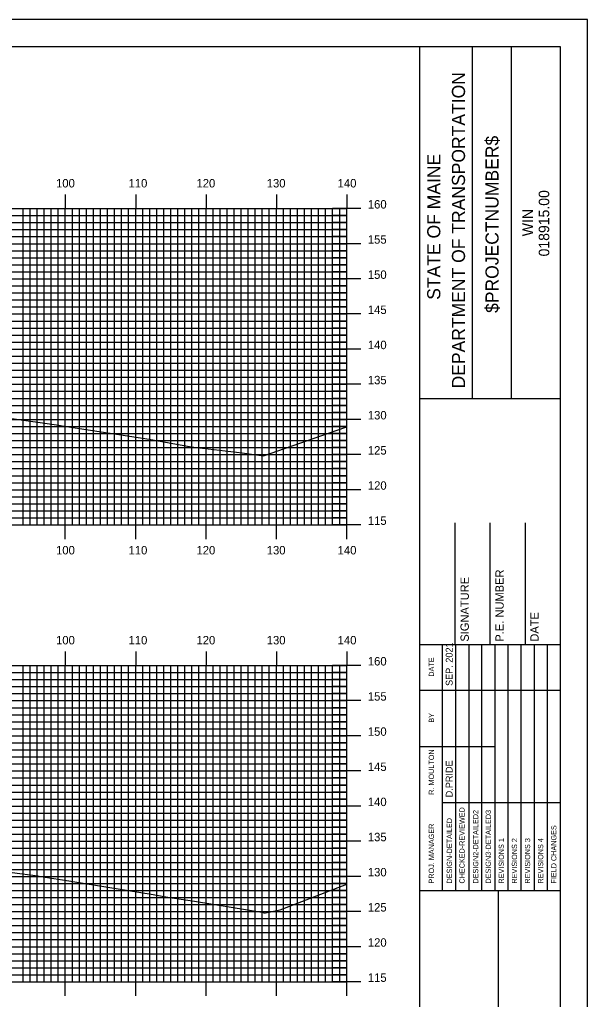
# Model space of a CAD drawing. Extents: x 851533 to 851876, y 366605 to 366825.
# Drawn here: x 851792 to 851872.7, y 366685.6 to 366824.9 of the extents above; entities that cross this region are included whole.
import ezdxf

# ---------------------------------------------------------------- set-up
doc = ezdxf.new("R2010")
doc.units = 0
for name, color, linetype in [('BORDER', 7, 'Continuous'), ('H_V ANNOTATION', 7, 'Continuous'), ('MAJOR', 7, 'Continuous'), ('MINOR', 7, 'Continuous'), ('PLOT BOUNDARY', 7, 'Continuous'), ('S_Roadway_Centerline', 7, 'Continuous')]:
    doc.layers.add(name, color=color, linetype=linetype)

msp = doc.modelspace()

# ---------------------------------------------------------------- linework, layer by layer
at = {"layer": 'BORDER'}
for p, q in [((851848.85, 366611.06), (851848.85, 366821.06)), ((851856.31, 366771.05), (851856.31, 366821.05)), ((851861.9, 366771.05), (851861.9, 366821.05)), ((851848.85, 366771.04), (851868.85, 366771.04)), ((851853.85, 366736.06), (851853.85, 366753.36)), ((851858.85, 366736.06), (851858.85, 366753.36)), ((851863.85, 366736.06), (851863.85, 366753.36)), ((851848.85, 366736.06), (851868.85, 366736.06)), ((851848.85, 366701.06), (851868.85, 366701.06)), ((851860.03, 366631.06), (851860.03, 366701.06))]:
    msp.add_line(p, q, dxfattribs=at)
msp.add_lwpolyline([(851548.85, 366611.06), (851868.85, 366611.06), (851868.85, 366821.06), (851548.85, 366821.06)], close=True, dxfattribs=at)
for points in [[(851852.08, 366729.56), (851852.08, 366736.06)], [(851853.95, 366701.07), (851853.95, 366736.06)], [(851855.81, 366736.06), (851855.81, 366701.07)], [(851857.67, 366701.07), (851857.67, 366736.06)], [(851859.54, 366701.07), (851859.54, 366736.06)], [(851861.4, 366701.07), (851861.4, 366736.06)], [(851863.26, 366701.07), (851863.26, 366736.06)], [(851865.13, 366701.07), (851865.13, 366736.06)], [(851866.99, 366701.07), (851866.99, 366736.06)], [(851852.08, 366701.07), (851852.08, 366734.65)], [(851848.85, 366729.56), (851868.85, 366729.56)], [(851848.85, 366721.56), (851852.08, 366721.56)], [(851852.08, 366721.56), (851859.53, 366721.56)], [(851852.08, 366713.56), (851868.85, 366713.56)]]:
    msp.add_lwpolyline(points, dxfattribs=at)
at = {"layer": 'MAJOR'}
for p, q in [((851798.45, 366800.06), (851798.45, 366798.06)), ((851808.45, 366800.06), (851808.45, 366798.06)), ((851818.45, 366800.06), (851818.45, 366798.06)), ((851828.45, 366800.06), (851828.45, 366798.06)), ((851838.45, 366800.06), (851838.45, 366798.06)), ((851558.45, 366798.06), (851838.45, 366798.06)), ((851558.45, 366798.06), (851838.45, 366798.06)), ((851798.45, 366753.06), (851798.45, 366798.06)), ((851808.45, 366753.06), (851808.45, 366798.06)), ((851818.45, 366753.06), (851818.45, 366798.06)), ((851828.45, 366753.06), (851828.45, 366798.06)), ((851840.46, 366798.06), (851836.45, 366798.06)), ((851838.45, 366753.06), (851838.45, 366798.06)), ((851838.45, 366753.06), (851838.45, 366798.06)), ((851558.45, 366793.06), (851838.45, 366793.06)), ((851840.46, 366793.06), (851836.45, 366793.06)), ((851558.45, 366788.06), (851838.45, 366788.06)), ((851840.46, 366788.06), (851836.45, 366788.06)), ((851558.45, 366783.06), (851838.45, 366783.06)), ((851840.46, 366783.06), (851836.45, 366783.06)), ((851558.45, 366778.06), (851838.45, 366778.06)), ((851840.46, 366778.06), (851836.45, 366778.06)), ((851558.45, 366773.06), (851838.45, 366773.06)), ((851840.46, 366773.06), (851836.45, 366773.06)), ((851558.45, 366768.06), (851838.45, 366768.06)), ((851840.46, 366768.06), (851836.45, 366768.06)), ((851558.45, 366763.06), (851838.45, 366763.06)), ((851840.46, 366763.06), (851836.45, 366763.06)), ((851558.45, 366758.06), (851838.45, 366758.06)), ((851840.46, 366758.06), (851836.45, 366758.06)), ((851558.45, 366753.06), (851838.45, 366753.06)), ((851558.45, 366753.06), (851838.45, 366753.06)), ((851798.45, 366751.05), (851798.45, 366753.06)), ((851808.45, 366751.05), (851808.45, 366753.06)), ((851818.45, 366751.05), (851818.45, 366753.06)), ((851828.45, 366751.05), (851828.45, 366753.06)), ((851840.46, 366753.06), (851836.45, 366753.06)), ((851838.45, 366751.05), (851838.45, 366753.06)), ((851798.45, 366735.06), (851798.45, 366733.06)), ((851808.45, 366735.06), (851808.45, 366733.06)), ((851818.45, 366735.06), (851818.45, 366733.06)), ((851828.45, 366735.06), (851828.45, 366733.06)), ((851838.45, 366735.06), (851838.45, 366733.06)), ((851558.45, 366733.06), (851838.45, 366733.06)), ((851558.45, 366733.06), (851838.45, 366733.06)), ((851798.45, 366688.06), (851798.45, 366733.06)), ((851808.45, 366688.06), (851808.45, 366733.06)), ((851818.45, 366688.06), (851818.45, 366733.06)), ((851828.45, 366688.06), (851828.45, 366733.06)), ((851840.46, 366733.06), (851836.45, 366733.06)), ((851838.45, 366688.06), (851838.45, 366733.06)), ((851838.45, 366688.06), (851838.45, 366733.06)), ((851558.45, 366728.06), (851838.45, 366728.06)), ((851840.46, 366728.06), (851836.45, 366728.06)), ((851558.45, 366723.06), (851838.45, 366723.06)), ((851840.46, 366723.06), (851836.45, 366723.06)), ((851558.45, 366718.06), (851838.45, 366718.06)), ((851840.46, 366718.06), (851836.45, 366718.06)), ((851558.45, 366713.06), (851838.45, 366713.06)), ((851840.46, 366713.06), (851836.45, 366713.06)), ((851558.45, 366708.06), (851838.45, 366708.06)), ((851840.46, 366708.06), (851836.45, 366708.06)), ((851558.45, 366703.06), (851838.45, 366703.06)), ((851840.46, 366703.06), (851836.45, 366703.06)), ((851558.45, 366698.06), (851838.45, 366698.06)), ((851840.46, 366698.06), (851836.45, 366698.06)), ((851558.45, 366693.06), (851838.45, 366693.06)), ((851840.46, 366693.06), (851836.45, 366693.06)), ((851558.45, 366688.06), (851838.45, 366688.06)), ((851558.45, 366688.06), (851838.45, 366688.06)), ((851798.45, 366686.05), (851798.45, 366688.06)), ((851808.45, 366686.05), (851808.45, 366688.06)), ((851818.45, 366686.05), (851818.45, 366688.06)), ((851828.45, 366686.05), (851828.45, 366688.06)), ((851840.46, 366688.06), (851836.45, 366688.06)), ((851838.45, 366686.05), (851838.45, 366688.06))]:
    msp.add_line(p, q, dxfattribs=at)
at = {"layer": 'MINOR'}
for p, q in [((851558.45, 366797.06), (851838.45, 366797.06)), ((851792.45, 366753.06), (851792.45, 366798.06)), ((851793.45, 366753.06), (851793.45, 366798.06)), ((851794.45, 366753.06), (851794.45, 366798.06)), ((851795.45, 366753.06), (851795.45, 366798.06)), ((851796.45, 366753.06), (851796.45, 366798.06)), ((851797.45, 366753.06), (851797.45, 366798.06)), ((851799.45, 366753.06), (851799.45, 366798.06)), ((851800.45, 366753.06), (851800.45, 366798.06)), ((851801.45, 366753.06), (851801.45, 366798.06)), ((851802.45, 366753.06), (851802.45, 366798.06)), ((851803.45, 366753.06), (851803.45, 366798.06)), ((851804.45, 366753.06), (851804.45, 366798.06)), ((851805.45, 366753.06), (851805.45, 366798.06)), ((851806.45, 366753.06), (851806.45, 366798.06)), ((851807.45, 366753.06), (851807.45, 366798.06)), ((851809.45, 366753.06), (851809.45, 366798.06)), ((851810.45, 366753.06), (851810.45, 366798.06)), ((851811.45, 366753.06), (851811.45, 366798.06)), ((851812.45, 366753.06), (851812.45, 366798.06)), ((851813.45, 366753.06), (851813.45, 366798.06)), ((851814.45, 366753.06), (851814.45, 366798.06)), ((851815.45, 366753.06), (851815.45, 366798.06)), ((851816.45, 366753.06), (851816.45, 366798.06)), ((851817.45, 366753.06), (851817.45, 366798.06)), ((851819.45, 366753.06), (851819.45, 366798.06)), ((851820.45, 366753.06), (851820.45, 366798.06)), ((851821.45, 366753.06), (851821.45, 366798.06)), ((851822.45, 366753.06), (851822.45, 366798.06)), ((851823.45, 366753.06), (851823.45, 366798.06)), ((851824.45, 366753.06), (851824.45, 366798.06)), ((851825.45, 366753.06), (851825.45, 366798.06)), ((851826.45, 366753.06), (851826.45, 366798.06)), ((851827.45, 366753.06), (851827.45, 366798.06)), ((851829.45, 366753.06), (851829.45, 366798.06)), ((851830.45, 366753.06), (851830.45, 366798.06)), ((851831.45, 366753.06), (851831.45, 366798.06)), ((851832.45, 366753.06), (851832.45, 366798.06)), ((851833.45, 366753.06), (851833.45, 366798.06)), ((851834.45, 366753.06), (851834.45, 366798.06)), ((851835.45, 366753.06), (851835.45, 366798.06)), ((851836.45, 366753.06), (851836.45, 366798.06)), ((851838.45, 366797.06), (851836.45, 366797.06)), ((851837.45, 366753.06), (851837.45, 366798.06)), ((851558.45, 366796.06), (851838.45, 366796.06)), ((851838.45, 366796.06), (851836.45, 366796.06)), ((851558.45, 366795.06), (851838.45, 366795.06)), ((851558.45, 366794.06), (851838.45, 366794.06)), ((851838.45, 366795.06), (851836.45, 366795.06)), ((851838.45, 366794.06), (851836.45, 366794.06)), ((851558.45, 366792.06), (851838.45, 366792.06)), ((851838.45, 366792.06), (851836.45, 366792.06)), ((851558.45, 366791.06), (851838.45, 366791.06)), ((851558.45, 366790.06), (851838.45, 366790.06)), ((851838.45, 366791.06), (851836.45, 366791.06)), ((851838.45, 366790.06), (851836.45, 366790.06)), ((851558.45, 366789.06), (851838.45, 366789.06)), ((851838.45, 366789.06), (851836.45, 366789.06)), ((851558.45, 366787.06), (851838.45, 366787.06)), ((851838.45, 366787.06), (851836.45, 366787.06)), ((851558.45, 366786.06), (851838.45, 366786.06)), ((851838.45, 366786.06), (851836.45, 366786.06)), ((851558.45, 366785.06), (851838.45, 366785.06)), ((851838.45, 366785.06), (851836.45, 366785.06)), ((851558.45, 366784.06), (851838.45, 366784.06)), ((851838.45, 366784.06), (851836.45, 366784.06)), ((851558.45, 366782.06), (851838.45, 366782.06)), ((851838.45, 366782.06), (851836.45, 366782.06)), ((851558.45, 366781.06), (851838.45, 366781.06)), ((851558.45, 366780.06), (851838.45, 366780.06)), ((851838.45, 366781.06), (851836.45, 366781.06)), ((851838.45, 366780.06), (851836.45, 366780.06)), ((851558.45, 366779.06), (851838.45, 366779.06)), ((851838.45, 366779.06), (851836.45, 366779.06)), ((851558.45, 366777.06), (851838.45, 366777.06)), ((851558.45, 366776.06), (851838.45, 366776.06)), ((851838.45, 366777.06), (851836.45, 366777.06)), ((851838.45, 366776.06), (851836.45, 366776.06)), ((851558.45, 366775.06), (851838.45, 366775.06)), ((851838.45, 366775.06), (851836.45, 366775.06)), ((851558.45, 366774.06), (851838.45, 366774.06)), ((851838.45, 366774.06), (851836.45, 366774.06)), ((851558.45, 366772.06), (851838.45, 366772.06)), ((851838.45, 366772.06), (851836.45, 366772.06)), ((851558.45, 366771.06), (851838.45, 366771.06)), ((851838.45, 366771.06), (851836.45, 366771.06)), ((851558.45, 366770.06), (851838.45, 366770.06)), ((851558.45, 366769.06), (851838.45, 366769.06)), ((851838.45, 366770.06), (851836.45, 366770.06)), ((851838.45, 366769.06), (851836.45, 366769.06)), ((851558.45, 366767.06), (851838.45, 366767.06)), ((851838.45, 366767.06), (851836.45, 366767.06)), ((851558.45, 366766.06), (851838.45, 366766.06)), ((851558.45, 366765.06), (851838.45, 366765.06)), ((851838.45, 366766.06), (851836.45, 366766.06)), ((851838.45, 366765.06), (851836.45, 366765.06)), ((851558.45, 366764.06), (851838.45, 366764.06)), ((851838.45, 366764.06), (851836.45, 366764.06)), ((851558.45, 366762.06), (851838.45, 366762.06)), ((851838.45, 366762.06), (851836.45, 366762.06)), ((851558.45, 366761.06), (851838.45, 366761.06)), ((851838.45, 366761.06), (851836.45, 366761.06)), ((851558.45, 366760.06), (851838.45, 366760.06)), ((851838.45, 366760.06), (851836.45, 366760.06)), ((851558.45, 366759.06), (851838.45, 366759.06)), ((851838.45, 366759.06), (851836.45, 366759.06)), ((851558.45, 366757.06), (851838.45, 366757.06)), ((851838.45, 366757.06), (851836.45, 366757.06)), ((851558.45, 366756.06), (851838.45, 366756.06)), ((851558.45, 366755.06), (851838.45, 366755.06)), ((851838.45, 366756.06), (851836.45, 366756.06)), ((851838.45, 366755.06), (851836.45, 366755.06)), ((851558.45, 366754.06), (851838.45, 366754.06)), ((851838.45, 366754.06), (851836.45, 366754.06)), ((851792.45, 366688.06), (851792.45, 366733.06)), ((851793.45, 366688.06), (851793.45, 366733.06)), ((851794.45, 366688.06), (851794.45, 366733.06)), ((851795.45, 366688.06), (851795.45, 366733.06)), ((851796.45, 366688.06), (851796.45, 366733.06)), ((851797.45, 366688.06), (851797.45, 366733.06)), ((851799.45, 366688.06), (851799.45, 366733.06)), ((851800.45, 366688.06), (851800.45, 366733.06)), ((851801.45, 366688.06), (851801.45, 366733.06)), ((851802.45, 366688.06), (851802.45, 366733.06)), ((851803.45, 366688.06), (851803.45, 366733.06)), ((851804.45, 366688.06), (851804.45, 366733.06)), ((851805.45, 366688.06), (851805.45, 366733.06)), ((851806.45, 366688.06), (851806.45, 366733.06)), ((851807.45, 366688.06), (851807.45, 366733.06)), ((851809.45, 366688.06), (851809.45, 366733.06)), ((851810.45, 366688.06), (851810.45, 366733.06)), ((851811.45, 366688.06), (851811.45, 366733.06)), ((851812.45, 366688.06), (851812.45, 366733.06)), ((851813.45, 366688.06), (851813.45, 366733.06)), ((851814.45, 366688.06), (851814.45, 366733.06)), ((851815.45, 366688.06), (851815.45, 366733.06)), ((851816.45, 366688.06), (851816.45, 366733.06)), ((851817.45, 366688.06), (851817.45, 366733.06)), ((851819.45, 366688.06), (851819.45, 366733.06)), ((851820.45, 366688.06), (851820.45, 366733.06)), ((851821.45, 366688.06), (851821.45, 366733.06)), ((851822.45, 366688.06), (851822.45, 366733.06)), ((851823.45, 366688.06), (851823.45, 366733.06)), ((851824.45, 366688.06), (851824.45, 366733.06)), ((851825.45, 366688.06), (851825.45, 366733.06)), ((851826.45, 366688.06), (851826.45, 366733.06)), ((851827.45, 366688.06), (851827.45, 366733.06)), ((851829.45, 366688.06), (851829.45, 366733.06)), ((851830.45, 366688.06), (851830.45, 366733.06)), ((851831.45, 366688.06), (851831.45, 366733.06)), ((851832.45, 366688.06), (851832.45, 366733.06)), ((851833.45, 366688.06), (851833.45, 366733.06)), ((851834.45, 366688.06), (851834.45, 366733.06)), ((851835.45, 366688.06), (851835.45, 366733.06)), ((851836.45, 366688.06), (851836.45, 366733.06)), ((851837.45, 366688.06), (851837.45, 366733.06)), ((851558.45, 366732.06), (851838.45, 366732.06)), ((851838.45, 366732.06), (851836.45, 366732.06)), ((851558.45, 366731.06), (851838.45, 366731.06)), ((851558.45, 366730.06), (851838.45, 366730.06)), ((851838.45, 366731.06), (851836.45, 366731.06)), ((851838.45, 366730.06), (851836.45, 366730.06)), ((851558.45, 366729.06), (851838.45, 366729.06)), ((851838.45, 366729.06), (851836.45, 366729.06)), ((851558.45, 366727.06), (851838.45, 366727.06)), ((851558.45, 366726.06), (851838.45, 366726.06)), ((851838.45, 366727.06), (851836.45, 366727.06)), ((851838.45, 366726.06), (851836.45, 366726.06)), ((851558.45, 366725.06), (851838.45, 366725.06)), ((851838.45, 366725.06), (851836.45, 366725.06)), ((851558.45, 366724.06), (851838.45, 366724.06)), ((851838.45, 366724.06), (851836.45, 366724.06)), ((851558.45, 366722.06), (851838.45, 366722.06)), ((851838.45, 366722.06), (851836.45, 366722.06)), ((851558.45, 366721.06), (851838.45, 366721.06)), ((851838.45, 366721.06), (851836.45, 366721.06)), ((851558.45, 366720.06), (851838.45, 366720.06)), ((851558.45, 366719.06), (851838.45, 366719.06)), ((851838.45, 366720.06), (851836.45, 366720.06)), ((851838.45, 366719.06), (851836.45, 366719.06)), ((851558.45, 366717.06), (851838.45, 366717.06)), ((851558.45, 366716.06), (851838.45, 366716.06)), ((851838.45, 366717.06), (851836.45, 366717.06)), ((851838.45, 366716.06), (851836.45, 366716.06)), ((851558.45, 366715.06), (851838.45, 366715.06)), ((851838.45, 366715.06), (851836.45, 366715.06)), ((851558.45, 366714.06), (851838.45, 366714.06)), ((851838.45, 366714.06), (851836.45, 366714.06)), ((851558.45, 366712.06), (851838.45, 366712.06)), ((851838.45, 366712.06), (851836.45, 366712.06)), ((851558.45, 366711.06), (851838.45, 366711.06)), ((851838.45, 366711.06), (851836.45, 366711.06)), ((851558.45, 366710.06), (851838.45, 366710.06)), ((851558.45, 366709.06), (851838.45, 366709.06)), ((851838.45, 366710.06), (851836.45, 366710.06)), ((851838.45, 366709.06), (851836.45, 366709.06)), ((851558.45, 366707.06), (851838.45, 366707.06)), ((851838.45, 366707.06), (851836.45, 366707.06)), ((851558.45, 366706.06), (851838.45, 366706.06)), ((851558.45, 366705.06), (851838.45, 366705.06)), ((851838.45, 366706.06), (851836.45, 366706.06)), ((851838.45, 366705.06), (851836.45, 366705.06)), ((851558.45, 366704.06), (851838.45, 366704.06)), ((851838.45, 366704.06), (851836.45, 366704.06)), ((851558.45, 366702.06), (851838.45, 366702.06)), ((851838.45, 366702.06), (851836.45, 366702.06)), ((851558.45, 366701.06), (851838.45, 366701.06)), ((851838.45, 366701.06), (851836.45, 366701.06)), ((851558.45, 366700.06), (851838.45, 366700.06)), ((851838.45, 366700.06), (851836.45, 366700.06)), ((851558.45, 366699.06), (851838.45, 366699.06)), ((851838.45, 366699.06), (851836.45, 366699.06)), ((851558.45, 366697.06), (851838.45, 366697.06)), ((851838.45, 366697.06), (851836.45, 366697.06)), ((851558.45, 366696.06), (851838.45, 366696.06)), ((851558.45, 366695.06), (851838.45, 366695.06)), ((851838.45, 366696.06), (851836.45, 366696.06)), ((851838.45, 366695.06), (851836.45, 366695.06)), ((851558.45, 366694.06), (851838.45, 366694.06)), ((851838.45, 366694.06), (851836.45, 366694.06)), ((851558.45, 366692.06), (851838.45, 366692.06)), ((851558.45, 366691.06), (851838.45, 366691.06)), ((851838.45, 366692.06), (851836.45, 366692.06)), ((851838.45, 366691.06), (851836.45, 366691.06)), ((851558.45, 366690.06), (851838.45, 366690.06)), ((851838.45, 366690.06), (851836.45, 366690.06)), ((851558.45, 366689.06), (851838.45, 366689.06)), ((851838.45, 366689.06), (851836.45, 366689.06))]:
    msp.add_line(p, q, dxfattribs=at)
at = {"layer": 'PLOT BOUNDARY'}
msp.add_lwpolyline([(851532.66, 366604.94), (851872.66, 366604.94), (851872.66, 366824.94), (851532.66, 366824.94)], close=True, dxfattribs=at)
at = {"layer": 'S_Roadway_Centerline'}
for points in [[(851790.53, 366768.26), (851797.51, 366767.23), (851798.02, 366767.16), (851810.39, 366765.24), (851816.33, 366764.17), (851823.59, 366763.31), (851826.64, 366762.89), (851828.64, 366763.58), (851836.96, 366766.5), (851838.45, 366767.02)], [(851790.9, 366703.61), (851794.55, 366703.13), (851794.98, 366703.06), (851798.06, 366702.56), (851810.63, 366700.52), (851813.03, 366700.09), (851816.8, 366699.52), (851826.68, 366697.91), (851826.69, 366697.84), (851828.97, 366698.29), (851838.45, 366701.94)]]:
    msp.add_lwpolyline(points, dxfattribs=at)

# ---------------------------------------------------------------- texts
at = {"layer": 'BORDER'}
for s, height, p in [('DEPARTMENT OF TRANSPORTATION', 1.8635, (851855.27, 366772.47)), ('$PROJECTNUMBER$', 1.8635, (851860.04, 366783.21)), ('STATE OF MAINE', 1.8635, (851851.76, 366785.08)), ('018915.00', 1.491, (851867.24, 366791.25)), ('WIN', 1.491, (851864.93, 366794.12)), ('P.E. NUMBER', 1.1811, (851860.77, 366736.45)), ('SIGNATURE', 1.181, (851855.81, 366736.45)), ('DATE', 1.181, (851865.73, 366736.45)), ('SEP. 2021', 0.969, (851853.5, 366730.15)), ('DATE', 0.743, (851850.86, 366731.47)), ('BY', 0.743, (851850.86, 366724.93)), ('R. MOULTON', 0.745, (851850.86, 366714.67)), ('D.PRIDE', 0.969, (851853.5, 366714.31)), ('CHECKED-REVIEWED', 0.7455, (851855.21, 366702.04)), ('DESIGN2-DETAILED2', 0.7455, (851857.15, 366702.04)), ('DESIGN3-DETAILED3', 0.7455, (851858.94, 366702.04)), ('DESIGN-DETAILED', 0.7455, (851853.42, 366702.04)), ('PROJ. MANAGER', 0.7455, (851850.86, 366702.04)), ('FIELD CHANGES', 0.7455, (851868.26, 366702.04)), ('REVISIONS 1', 0.7455, (851860.8, 366702.04)), ('REVISIONS 2', 0.7455, (851862.67, 366702.04)), ('REVISIONS 3', 0.7455, (851864.53, 366702.04)), ('REVISIONS 4', 0.7455, (851866.39, 366702.04))]:
    msp.add_text(s, height=height, rotation=90, dxfattribs=at).set_placement(p)
at = {"layer": 'H_V ANNOTATION'}
for s, p in [('100', (851797.13, 366801.06)), ('110', (851807.43, 366801.06)), ('120', (851817.09, 366801.06)), ('130', (851827.08, 366801.06)), ('140', (851837.16, 366801.06)), ('160', (851841.45, 366798.06)), ('155', (851841.45, 366793.06)), ('150', (851841.45, 366788.06)), ('145', (851841.45, 366783.06)), ('140', (851841.45, 366778.06)), ('135', (851841.45, 366773.06)), ('130', (851841.45, 366768.06)), ('125', (851841.45, 366763.06)), ('120', (851841.45, 366758.06)), ('115', (851841.45, 366753.06)), ('100', (851797.13, 366748.86)), ('110', (851807.43, 366748.86)), ('120', (851817.09, 366748.86)), ('130', (851827.08, 366748.86)), ('140', (851837.16, 366748.86)), ('100', (851797.13, 366736.06)), ('110', (851807.43, 366736.06)), ('120', (851817.09, 366736.06)), ('130', (851827.08, 366736.06)), ('140', (851837.16, 366736.06)), ('160', (851841.45, 366733.06)), ('155', (851841.45, 366728.06)), ('150', (851841.45, 366723.06)), ('145', (851841.45, 366718.06)), ('140', (851841.45, 366713.06)), ('135', (851841.45, 366708.06)), ('130', (851841.45, 366703.06)), ('125', (851841.45, 366698.06)), ('120', (851841.45, 366693.06)), ('115', (851841.45, 366688.06))]:
    msp.add_text(s, height=1.2, dxfattribs=at).set_placement(p)

doc.saveas('drawing.dxf')
